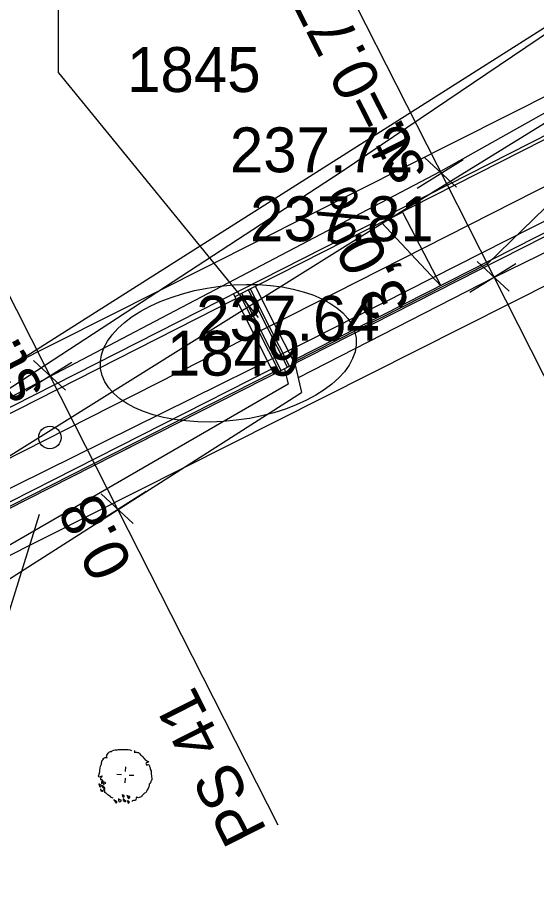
# Model space of a CAD drawing. Extents: x -601754 to -601440, y -1201912 to -1200862.
# Drawn here: x -601557.66 to -601534.51, y -1201609.03 to -1201570.54 of the extents above; entities that cross this region are included whole.
import ezdxf

# ---------------------------------------------------------------- set-up
doc = ezdxf.new("R2010")
doc.units = 0
for name, color, linetype in [('Hranice parcel', 7, 'Continuous'), ('Parcelní čísla', 7, 'Continuous'), ('u_dotčené parcely', 7, 'Continuous'), ('u_drén', 7, 'Continuous'), ('u_hrany', 7, 'Continuous'), ('u_krizky', 7, 'Continuous'), ('u_návrh', 7, 'Continuous'), ('u_osa', 7, 'Continuous'), ('u_popis', 7, 'Continuous'), ('u_pricne_cesta', 7, 'Continuous'), ('u_příčný odvodňovací žlab', 7, 'Continuous'), ('u_sklony', 7, 'Continuous'), ('u_staniceni', 7, 'Continuous'), ('u_terénní úpravy', 7, 'Continuous'), ('u_vysadba', 7, 'Continuous'), ('u_vyska', 7, 'Continuous')]:
    doc.layers.add(name, color=color, linetype=linetype)

msp = doc.modelspace()

# ---------------------------------------------------------------- linework, layer by layer
at = {"layer": 'Hranice parcel'}
for p, q in [((-601558.04, -1201586.08), (-601519.33, -1201566.6)), ((-601567.44, -1201599.25), (-601518.5, -1201574.62))]:
    msp.add_line(p, q, dxfattribs=at)
at = {"layer": 'u_dotčené parcely'}
msp.add_ellipse((-601548.255, -1201585.496), major_axis=(-5.691, -0.683), ratio=0.524694, dxfattribs=at)
at = {"layer": 'u_drén'}
msp.add_line((-601527.37, -1201572.458), (-601536.713, -1201581.517), dxfattribs=at)
for points in [[(-601536.713, -1201581.517), (-601545.332, -1201585.89)], [(-601546.251, -1201586.356), (-601566.954, -1201596.862)]]:
    msp.add_lwpolyline(points, dxfattribs=at)
at = {"layer": 'u_hrany'}
for points in [[(-601517.05, -1201548.75), (-601518.98, -1201555.47), (-601521.95, -1201561.09), (-601526.18, -1201565.91), (-601543.22, -1201577.44), (-601564.63, -1201591.39), (-601571.15, -1201595.24), (-601583.39, -1201600.55), (-601590.31, -1201602.43), (-601596.71, -1201602.74)], [(-601583.7, -1201599.06), (-601568.87, -1201592.97), (-601526.18, -1201565.91)], [(-601596.47, -1201605.31), (-601590.64, -1201604.85), (-601581.97, -1201602.55), (-601570.67, -1201597.77), (-601563.01, -1201593.18), (-601542.69, -1201580.51), (-601524.37, -1201569.19), (-601517.89, -1201568.67), (-601514.2, -1201569.51), (-601511.31, -1201571.5), (-601509.75, -1201574.25)], [(-601570.67, -1201597.77), (-601544.7, -1201584.94), (-601517.03, -1201570.93)]]:
    msp.add_lwpolyline(points, dxfattribs=at)
at = {"layer": 'u_krizky'}
for p, q in [((-601537.794, -1201576.879), (-601539.846, -1201578.159)), ((-601538.087, -1201578.106), (-601539.513, -1201576.786)), ((-601535.443, -1201581.511), (-601537.496, -1201582.791)), ((-601535.736, -1201582.738), (-601537.163, -1201581.418)), ((-601555.218, -1201585.907), (-601557.271, -1201587.187)), ((-601555.512, -1201587.134), (-601556.938, -1201585.814)), ((-601552.201, -1201591.853), (-601554.254, -1201593.133)), ((-601552.494, -1201593.08), (-601553.921, -1201591.76))]:
    msp.add_line(p, q, dxfattribs=at)
at = {"layer": 'u_návrh'}
for points in [[(-601527.41, -1201572.394), (-601577.234, -1201597.68)], [(-601527.336, -1201572.525), (-601547.959, -1201582.99)], [(-601525.672, -1201575.829), (-601545.366, -1201585.823)], [(-601525.602, -1201575.967), (-601575.363, -1201601.214)], [(-601547.914, -1201583.079), (-601577.118, -1201597.899)], [(-601546.329, -1201586.203), (-601575.48, -1201600.993)]]:
    msp.add_lwpolyline(points, dxfattribs=at)
at = {"layer": 'u_osa'}
msp.add_lwpolyline([(-601512.379, -1201413.946), (-601514.108, -1201444.311), (-601514.27, -1201450.211), (-601514.083, -1201456.11), (-601513.549, -1201461.987), (-601508.334, -1201505.161), (-601507.905, -1201509.51), (-601507.667, -1201513.873), (-601507.619, -1201518.242), (-601508.035, -1201556.382), (-601508.399, -1201559.4), (-601509.407, -1201562.268), (-601511.012, -1201564.849), (-601513.137, -1201567.023), (-601515.682, -1201568.685), (-601576.299, -1201599.446)], dxfattribs=at)
at = {"layer": 'u_popis'}
msp.add_line((-601555.82, -1201573.011), (-601546.92, -1201583.904), dxfattribs=at)
for points in [[(-601555.82, -1201573.011), (-601555.82, -1201529.46), (-601555.82, -1201529.46)], [(-601562.624, -1201708.991), (-601562.624, -1201611.788), (-601556.669, -1201592.66)]]:
    msp.add_lwpolyline(points, dxfattribs=at)
at = {"layer": 'u_pricne_cesta'}
for points in [[(-601528.534, -1201597.635), (-601537.585, -1201579.8), (-601546.635, -1201561.965)], [(-601546.034, -1201606.515), (-601555.084, -1201588.68), (-601564.135, -1201570.845)]]:
    msp.add_lwpolyline(points, dxfattribs=at)
at = {"layer": 'u_příčný odvodňovací žlab'}
for points in [[(-601546.216, -1201586.425), (-601547.122, -1201584.64), (-601548.027, -1201582.856)], [(-601545.904, -1201586.267), (-601546.81, -1201584.481), (-601547.647, -1201582.832)], [(-601545.609, -1201586.118), (-601546.515, -1201584.332), (-601547.353, -1201582.682)], [(-601545.52, -1201586.073), (-601546.426, -1201584.287), (-601547.263, -1201582.637)], [(-601545.297, -1201585.959), (-601546.203, -1201584.174), (-601547.041, -1201582.524)], [(-601545.993, -1201586.312), (-601546.899, -1201584.527), (-601547.736, -1201582.877)]]:
    msp.add_lwpolyline(points, dxfattribs=at)
at = {"layer": 'u_sklony'}
for p, q in [((-601553.306, -1201590.023), (-601551.846, -1201589.282)), ((-601551.917, -1201591.653), (-601553.182, -1201592.46))]:
    msp.add_line(p, q, dxfattribs=at)
msp.add_lwpolyline([(-601540.5, -1201579.21), (-601538.79, -1201582.492), (-601541.433, -1201579.678)], close=True, dxfattribs=at)
at = {"layer": 'u_staniceni'}
msp.add_circle((-601556.202, -1201589.248), 0.5, dxfattribs=at)
at = {"layer": 'u_terénní úpravy'}
for p, q in [((-601545.756, -1201586.192), (-601545.593, -1201586.88)), ((-601545.297, -1201585.959), (-601544.993, -1201587.238))]:
    msp.add_line(p, q, dxfattribs=at)
for points in [[(-601514.933, -1201414.628), (-601516.331, -1201434.631), (-601517.226, -1201443.324), (-601517.513, -1201450.183), (-601517.731, -1201454.987), (-601515.193, -1201475.061), (-601512.311, -1201494.835), (-601511.289, -1201505.249), (-601511.001, -1201509.503), (-601510.74, -1201514.546), (-601511.195, -1201526.596), (-601511.285, -1201528.955), (-601511.232, -1201535.024), (-601513.147, -1201556.002), (-601514.131, -1201558.519), (-601515.245, -1201561.131), (-601516.655, -1201563.291), (-601517.726, -1201564.657), (-601519.33, -1201566.6), (-601521.678, -1201567.781), (-601538.799, -1201577.408), (-601577.284, -1201597.587)], [(-601510.358, -1201585.479), (-601510.939, -1201583.156), (-601511.905, -1201580.866), (-601513.234, -1201579.022), (-601515.173, -1201577.212), (-601516.815, -1201576.086), (-601517.621, -1201575.775), (-601519.795, -1201575.475), (-601521.737, -1201575.568), (-601523.807, -1201575.966), (-601536.406, -1201582.122), (-601545.145, -1201586.599)], [(-601545.593, -1201586.88), (-601568.271, -1201599.969)], [(-601565.539, -1201600.34), (-601544.993, -1201587.238)]]:
    msp.add_lwpolyline(points, dxfattribs=at)
at = {"layer": 'u_vysadba'}
for points in [[(-601553.83, -1201603.573), (-601553.829, -1201603.544), (-601553.769, -1201603.518), (-601553.739, -1201603.505), (-601553.709, -1201603.492), (-601553.679, -1201603.494), (-601553.65, -1201603.495), (-601553.663, -1201603.465), (-601553.676, -1201603.435), (-601553.659, -1201603.392), (-601553.643, -1201603.349), (-601553.611, -1201603.307), (-601553.58, -1201603.279), (-601553.55, -1201603.251), (-601553.504, -1201603.225), (-601553.46, -1201603.227), (-601553.43, -1201603.199), (-601553.355, -1201603.174), (-601553.296, -1201603.162), (-601553.251, -1201603.15), (-601553.193, -1201603.153), (-601553.148, -1201603.141), (-601553.105, -1201603.143), (-601553.032, -1201603.147), (-601552.958, -1201603.136), (-601552.885, -1201603.14), (-601552.797, -1201603.145), (-601552.71, -1201603.149), (-601552.637, -1201603.153), (-601552.593, -1201603.17), (-601552.565, -1201603.186)], [(-601552.418, -1201603.179), (-601552.434, -1201603.208), (-601552.436, -1201603.237), (-601552.452, -1201603.266), (-601552.408, -1201603.253), (-601552.378, -1201603.255), (-601552.349, -1201603.256), (-601552.306, -1201603.273), (-601552.262, -1201603.276), (-601552.22, -1201603.307), (-601552.192, -1201603.338), (-601552.165, -1201603.383), (-601552.123, -1201603.415), (-601552.067, -1201603.462), (-601552.026, -1201603.508), (-601551.998, -1201603.538), (-601551.957, -1201603.599), (-601551.9, -1201603.631), (-601551.858, -1201603.663), (-601551.815, -1201603.68), (-601551.817, -1201603.709)], [(-601553.83, -1201603.573), (-601553.831, -1201603.588), (-601553.877, -1201603.63), (-601553.908, -1201603.657), (-601553.91, -1201603.701), (-601553.912, -1201603.745), (-601553.915, -1201603.803), (-601553.932, -1201603.846), (-601553.949, -1201603.875), (-601553.965, -1201603.903), (-601553.982, -1201603.961), (-601553.984, -1201603.99), (-601553.987, -1201604.048), (-601553.989, -1201604.092), (-601553.991, -1201604.121), (-601554.009, -1201604.194), (-601554.026, -1201604.237), (-601554.029, -1201604.28), (-601554.045, -1201604.309), (-601554.032, -1201604.339), (-601553.989, -1201604.356), (-601553.899, -1201604.331), (-601553.869, -1201604.318), (-601553.902, -1201604.375), (-601553.932, -1201604.403), (-601553.949, -1201604.431), (-601553.951, -1201604.475), (-601553.922, -1201604.476), (-601553.878, -1201604.479), (-601553.865, -1201604.509), (-601553.882, -1201604.552), (-601553.898, -1201604.58), (-601553.9, -1201604.624), (-601553.903, -1201604.668)], [(-601552.831, -1201604.115), (-601552.82, -1201603.911)], [(-601551.817, -1201603.709), (-601551.861, -1201603.721), (-601551.906, -1201603.734), (-601551.922, -1201603.762), (-601551.909, -1201603.792), (-601551.882, -1201603.837), (-601551.852, -1201603.824), (-601551.807, -1201603.812), (-601551.78, -1201603.843), (-601551.767, -1201603.873), (-601551.768, -1201603.902), (-601551.742, -1201603.962), (-601551.73, -1201604.007), (-601551.718, -1201604.051), (-601551.691, -1201604.096), (-601551.692, -1201604.126), (-601551.694, -1201604.169), (-601551.696, -1201604.199), (-601551.684, -1201604.243), (-601551.672, -1201604.302), (-601551.675, -1201604.361), (-601551.664, -1201604.42), (-601551.665, -1201604.449), (-601551.667, -1201604.478), (-601551.669, -1201604.522), (-601551.7, -1201604.55), (-601551.701, -1201604.579), (-601551.718, -1201604.622), (-601551.735, -1201604.651), (-601551.781, -1201604.692), (-601551.784, -1201604.75), (-601551.801, -1201604.808), (-601551.82, -1201604.88), (-601551.867, -1201604.936), (-601551.9, -1201605.008), (-601551.932, -1201605.065), (-601551.992, -1201605.091), (-601552.023, -1201605.119), (-601552.069, -1201605.16), (-601552.1, -1201605.202), (-601552.117, -1201605.245), (-601552.177, -1201605.271), (-601552.222, -1201605.284), (-601552.252, -1201605.297), (-601552.295, -1201605.28), (-601552.338, -1201605.263), (-601552.355, -1201605.306), (-601552.373, -1201605.364), (-601552.389, -1201605.407), (-601552.434, -1201605.419), (-601552.478, -1201605.417)], [(-601553.014, -1201604.266), (-601553.219, -1201604.256)], [(-601552.664, -1201604.285), (-601552.459, -1201604.281)], [(-601554.034, -1201604.661), (-601554.021, -1201604.691), (-601554.009, -1201604.735), (-601553.996, -1201604.765), (-601553.997, -1201604.795), (-601553.969, -1201604.811), (-601553.938, -1201604.783), (-601553.892, -1201604.742), (-601553.921, -1201604.74), (-601553.963, -1201604.709), (-601554.006, -1201604.692)], [(-601553.876, -1201604.728), (-601553.835, -1201604.774), (-601553.793, -1201604.82), (-601553.751, -1201604.852)], [(-601553.751, -1201604.852), (-601553.78, -1201604.85), (-601553.81, -1201604.848), (-601553.839, -1201604.847), (-601553.852, -1201604.817), (-601553.85, -1201604.788), (-601553.863, -1201604.758)], [(-601553.852, -1201604.539), (-601553.854, -1201604.583), (-601553.841, -1201604.613), (-601553.829, -1201604.657), (-601553.816, -1201604.687), (-601553.787, -1201604.689), (-601553.77, -1201604.66), (-601553.71, -1201604.634), (-601553.753, -1201604.617), (-601553.782, -1201604.601), (-601553.839, -1201604.569)], [(-601552.847, -1201604.422), (-601552.858, -1201604.626)], [(-601553.944, -1201604.9), (-601553.934, -1201604.988), (-601553.89, -1201604.991), (-601553.861, -1201604.992), (-601553.817, -1201604.98), (-601553.874, -1201604.962), (-601553.918, -1201604.96), (-601553.931, -1201604.93)], [(-601553.38, -1201605.31), (-601553.423, -1201605.294), (-601553.452, -1201605.277), (-601553.481, -1201605.276), (-601553.508, -1201605.23), (-601553.536, -1201605.214), (-601553.578, -1201605.183), (-601553.621, -1201605.166), (-601553.663, -1201605.12), (-601553.691, -1201605.089), (-601553.762, -1201605.056), (-601553.76, -1201605.012), (-601553.757, -1201604.968), (-601553.77, -1201604.938), (-601553.799, -1201604.922), (-601553.767, -1201604.88), (-601553.738, -1201604.882)], [(-601552.976, -1201605.141), (-601552.965, -1201605.215), (-601552.938, -1201605.261), (-601552.894, -1201605.248), (-601552.892, -1201605.219), (-601552.891, -1201605.19), (-601552.934, -1201605.173), (-601552.962, -1201605.157)], [(-601552.773, -1201605.181), (-601552.747, -1201605.241), (-601552.735, -1201605.286), (-601552.707, -1201605.317), (-601552.677, -1201605.304), (-601552.645, -1201605.261), (-601552.644, -1201605.232), (-601552.688, -1201605.23), (-601552.716, -1201605.214), (-601552.745, -1201605.198), (-601552.774, -1201605.196)], [(-601553.369, -1201605.37), (-601553.273, -1201605.492), (-601553.246, -1201605.537), (-601553.214, -1201605.495), (-601553.213, -1201605.466), (-601553.241, -1201605.45), (-601553.284, -1201605.433), (-601553.312, -1201605.416), (-601553.341, -1201605.4)], [(-601553.146, -1201605.323), (-601553.15, -1201605.396), (-601553.138, -1201605.44), (-601553.11, -1201605.471), (-601553.051, -1201605.46), (-601553.02, -1201605.432), (-601553.034, -1201605.402), (-601553.077, -1201605.385), (-601553.12, -1201605.368)], [(-601552.941, -1201605.319), (-601552.858, -1201605.397), (-601552.829, -1201605.413), (-601552.816, -1201605.443), (-601552.847, -1201605.47), (-601552.876, -1201605.469), (-601552.889, -1201605.439), (-601552.916, -1201605.394), (-601552.944, -1201605.363)], [(-601552.742, -1201605.432), (-601552.732, -1201605.506), (-601552.718, -1201605.536), (-601552.688, -1201605.523), (-601552.657, -1201605.48), (-601552.685, -1201605.45), (-601552.713, -1201605.434), (-601552.742, -1201605.432)], [(-601552.478, -1201605.417), (-601552.522, -1201605.429), (-601552.553, -1201605.457)]]:
    msp.add_lwpolyline(points, dxfattribs=at)

# ---------------------------------------------------------------- texts
at = {"layer": 'Parcelní čísla'}
for s, p in [('1845', (-601552.765, -1201573.866)), ('1849', (-601550.987, -1201586.496))]:
    msp.add_text(s, height=2, dxfattribs=at).set_placement(p)
at = {"layer": 'u_pricne_cesta'}
for s, p in [('st.=0.77912', (-601539.382, -1201577.424)), ('st.=0.79874', (-601556.447, -1201587.161)), ('PS 41', (-601546.504, -1201606.754))]:
    msp.add_text(s, height=2, rotation=116.9057, dxfattribs=at).set_placement(p)
at = {"layer": 'u_sklony'}
msp.add_text('3,0%', height=2, rotation=116.0267, dxfattribs=at).set_placement((-601540.095, -1201583.344))
at = {"layer": 'u_staniceni'}
msp.add_text('0.8', height=2, rotation=116.2559, dxfattribs=at).set_placement((-601552.472, -1201594.922))
at = {"layer": 'u_vyska'}
for s, p in [('237.72', (-601548.185, -1201577.44)), ('237.81', (-601547.282, -1201580.51)), ('237.64', (-601549.684, -1201584.94))]:
    msp.add_text(s, height=2, dxfattribs=at).set_placement(p)

doc.saveas('drawing.dxf')
